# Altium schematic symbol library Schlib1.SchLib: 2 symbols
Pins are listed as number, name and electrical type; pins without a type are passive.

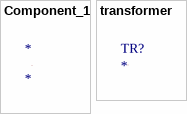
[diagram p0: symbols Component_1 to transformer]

## Component_1
designator *

## transformer
designator TR?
